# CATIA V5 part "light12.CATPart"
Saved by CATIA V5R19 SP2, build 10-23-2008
Part number: light12
Bounding box of the stored display mesh (mm): x 1605.744 to 1765.695, y -545.933 to 545.933, z 411.017 to 481.23
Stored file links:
  C:\BEHROOZ\catia learning\tarh haye mashin\hb\light12.CATPart
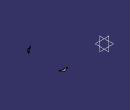
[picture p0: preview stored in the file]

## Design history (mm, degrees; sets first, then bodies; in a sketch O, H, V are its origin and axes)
Body1 (main body)
  Set1
    DatumSurface1
    ThickSurface1: Surface DatumSurface1, TopOffset 1, BotOffset 0
    DatumSurface2
    ThickSurface2: Surface DatumSurface2, TopOffset 1, BotOffset 0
